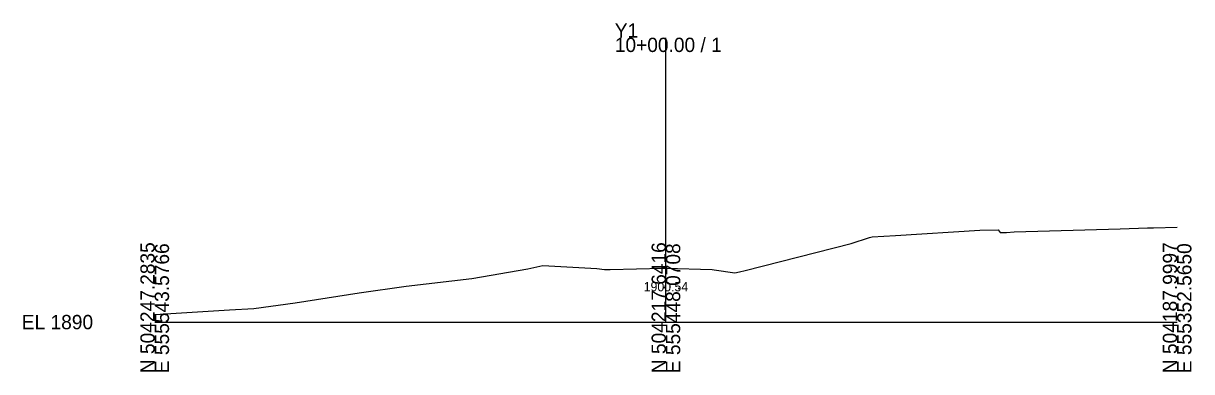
# Model space of a CAD drawing. Extents: x -26 to 1503, y -10 to 5015.
# Drawn here: x -25.7 to 202.8, y -9.7 to 58.4 of the extents above; entities that cross this region are included whole.
import ezdxf

# ---------------------------------------------------------------- set-up
doc = ezdxf.new("R2010")
doc.units = 0
for name, color, linetype in [('Default', 7, 'Continuous'), ('Exist Cross Section Cell', 7, 'Continuous'), ('Exist XS Center Line Elevation Label', 7, 'Continuous'), ('Exist XS Ground Line', 7, 'Continuous')]:
    doc.layers.add(name, color=color, linetype=linetype)

msp = doc.modelspace()

# ---------------------------------------------------------------- linework, layer by layer
at = {"layer": 'Exist Cross Section Cell'}
for p, q in [((100, 0), (100, 55.61)), ((0, 0), (100, 0)), ((100, 0), (200, 0))]:
    msp.add_line(p, q, dxfattribs=at)
at = {"layer": 'Exist XS Ground Line'}
for p, q in [((188.85, 18.21), (194.18, 18.41)), ((194.18, 18.41), (195.4, 18.43)), ((195.4, 18.43), (200, 18.54)), ((136.22, 15.38), (139.8, 16.54)), ((139.8, 16.54), (140.32, 16.69)), ((140.32, 16.69), (144.93, 16.9)), ((144.93, 16.9), (161.38, 17.98)), ((161.38, 17.98), (164.98, 18.01)), ((164.98, 18.01), (165.4, 17.52)), ((165.4, 17.52), (166.65, 17.54)), ((166.65, 17.54), (168.11, 17.63)), ((168.11, 17.63), (188.85, 18.21)), ((115.52, 10.11), (136.22, 15.38)), ((62.04, 8.49), (72.97, 10.39)), ((72.97, 10.39), (75.94, 11.03)), ((75.94, 11.03), (86.5, 10.45)), ((86.5, 10.45), (87.96, 10.31)), ((87.96, 10.31), (88.78, 10.29)), ((88.78, 10.29), (89.11, 10.3)), ((89.11, 10.3), (99.41, 10.56)), ((99.41, 10.56), (100, 10.54)), ((100, 10.54), (109.04, 10.26)), ((109.04, 10.26), (109.43, 10.2)), ((109.43, 10.2), (113.51, 9.66)), ((113.51, 9.66), (114.41, 9.84)), ((114.41, 9.84), (115.52, 10.11)), ((40, 5.71), (49.19, 7.03)), ((49.19, 7.03), (62.04, 8.49)), ((27.48, 3.79), (40, 5.71)), ((0, 1.48), (14.62, 2.36)), ((14.62, 2.36), (19.38, 2.66)), ((19.38, 2.66), (27.48, 3.79))]:
    msp.add_line(p, q, dxfattribs=at)

# ---------------------------------------------------------------- texts
at = {"layer": 'Default'}
msp.add_text('-', height=0.0001, dxfattribs=at).set_placement((0, 0))
at = {"layer": 'Exist Cross Section Cell'}
for s, p in [('Y1', (90, 55.61)), ('10+00.00 / 1', (90, 52.81)), ('EL 1890', (-26, -1.4))]:
    msp.add_text(s, height=2.8, dxfattribs=at).set_placement(p)
for s, p in [('N 504247.2835', (0, -10)), ('E 555543.5766', (2.8, -10)), ('N 504217.6416', (100, -10)), ('E 555448.0708', (102.8, -10)), ('N 504187.9997', (200, -10)), ('E 555352.5650', (202.8, -10))]:
    msp.add_text(s, height=2.8, rotation=90, dxfattribs=at).set_placement(p)
at = {"layer": 'Exist XS Center Line Elevation Label'}
msp.add_text('1900.54', height=1.8, dxfattribs=at).set_placement((95.65, 6.01))

doc.saveas('drawing.dxf')
